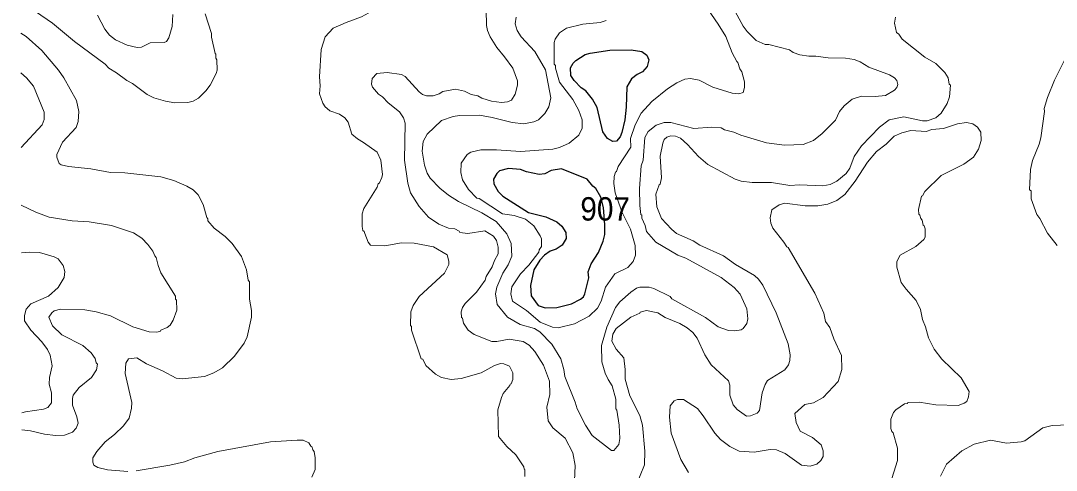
# Model space of a CAD drawing. Extents: x 447.8 to 473.9, y 7733.1 to 7760.8.
# Drawn here: x 447.849 to 451.388, y 7735.931 to 7737.469 of the extents above; entities that cross this region are included whole.
import ezdxf

# ---------------------------------------------------------------- set-up
doc = ezdxf.new("R2010")
doc.units = 0
doc.header["$LTSCALE"] = 0.032
doc.layers.add('1', color=7, linetype='Continuous', lineweight=25)
doc.layers.add('2', color=7, linetype='Continuous', lineweight=13)
doc.layers.add('21', color=7, linetype='Continuous')

msp = doc.modelspace()

# ---------------------------------------------------------------- linework, layer by layer
at = {"layer": '1'}
for points in [[(449.8538, 7737.0657), (449.8377, 7737.0891), (449.8186, 7737.1718), (449.8023, 7737.2009), (449.7799, 7737.2289), (449.7641, 7737.2393), (449.7396, 7737.2646), (449.7288, 7737.2812), (449.7277, 7737.3073), (449.7371, 7737.3243), (449.7459, 7737.3331), (449.7778, 7737.3529), (449.7946, 7737.3585), (449.8619, 7737.3681), (449.9348, 7737.3697), (449.9717, 7737.3633), (449.9879, 7737.351), (449.9949, 7737.3353), (449.9899, 7737.3128), (449.9731, 7737.2942), (449.9557, 7737.2856), (449.9363, 7737.2701), (449.9198, 7737.2433), (449.918, 7737.1727), (449.9131, 7737.1294), (449.9034, 7737.0865), (449.8967, 7737.0718), (449.8848, 7737.0564), (449.8724, 7737.0559)], [(449.7896, 7736.5891), (449.7883, 7736.6097), (449.7976, 7736.6376), (449.8226, 7736.6765), (449.8393, 7736.7146), (449.8446, 7736.7381), (449.8451, 7736.7711), (449.8403, 7736.83), (449.8314, 7736.8655), (449.8146, 7736.8952), (449.8042, 7736.9031), (449.7841, 7736.9264), (449.6967, 7736.9625), (449.6616, 7736.9561), (449.6403, 7736.9457), (449.6202, 7736.9426), (449.5773, 7736.9524), (449.5565, 7736.9602), (449.5156, 7736.9633), (449.4849, 7736.9551), (449.4756, 7736.9465), (449.4648, 7736.9273), (449.4651, 7736.9112), (449.4806, 7736.8846), (449.4965, 7736.8685), (449.5839, 7736.8125), (449.6426, 7736.7981), (449.6804, 7736.7808), (449.6984, 7736.7661), (449.7112, 7736.745), (449.7126, 7736.7242), (449.6995, 7736.7009), (449.6788, 7736.6875), (449.6584, 7736.6804), (449.6385, 7736.6669), (449.6225, 7736.6502), (449.6023, 7736.6162), (449.591, 7736.563), (449.5936, 7736.5282), (449.6175, 7736.4945), (449.6407, 7736.4865), (449.6811, 7736.4873), (449.7311, 7736.5006), (449.7622, 7736.5159), (449.7718, 7736.5239), (449.777, 7736.5349)]]:
    msp.add_lwpolyline(points, close=True, dxfattribs=at)
at = {"layer": '2'}
for points in [[(451.5688, 7737.5655), (451.4588, 7737.425), (451.4404, 7737.3933), (451.4375, 7737.3812), (451.4218, 7737.3529), (451.42, 7737.3431), (451.382, 7737.2653), (451.3575, 7737.2064)], [(447.8597, 7737.5276), (447.9567, 7737.4612), (448.0319, 7737.398), (448.1367, 7737.3202), (448.1492, 7737.3063), (448.1759, 7737.2908), (448.2112, 7737.2641), (448.2305, 7737.2547), (448.2802, 7737.2168), (448.3039, 7737.2053), (448.3434, 7737.1935), (448.3754, 7737.1879), (448.4197, 7737.1895), (448.4377, 7737.194), (448.456, 7737.204), (448.4815, 7737.2287), (448.4961, 7737.2489), (448.5167, 7737.2885), (448.5199, 7737.3), (448.5184, 7737.335), (448.5153, 7737.3404), (448.5152, 7737.3542), (448.5126, 7737.3572), (448.501, 7737.4132), (448.5008, 7737.4251), (448.4791, 7737.4928)], [(449.114, 7737.5314), (449.114, 7737.5248), (449.1095, 7737.517), (449.051, 7737.5029), (449.0128, 7737.4823), (448.9606, 7737.4634)], [(449.4387, 7737.5065), (449.4406, 7737.4525), (449.4438, 7737.4352), (449.453, 7737.4141), (449.4752, 7737.3773), (449.5017, 7737.346), (449.53, 7737.3064), (449.546, 7737.2636), (449.546, 7737.2484), (449.5389, 7737.2176), (449.5255, 7737.1972), (449.5121, 7737.191), (449.4911, 7737.1895), (449.4575, 7737.194), (449.4244, 7737.2046), (449.4111, 7737.2119), (449.3883, 7737.2169), (449.3654, 7737.2275), (449.3344, 7737.2351), (449.2907, 7737.2271), (449.2789, 7737.2193), (449.2577, 7737.2119), (449.2355, 7737.2117), (449.2217, 7737.2166), (449.2099, 7737.2252), (449.1624, 7737.2779), (449.1494, 7737.285), (449.1013, 7737.292), (449.0658, 7737.2881), (449.0495, 7737.2716), (449.0476, 7737.2523), (449.0509, 7737.2417), (449.0709, 7737.2175), (449.0848, 7737.2088), (449.1038, 7737.1886), (449.1434, 7737.1575), (449.1569, 7737.1371), (449.1629, 7737.1188), (449.1598, 7736.9923), (449.1711, 7736.913), (449.1807, 7736.8798), (449.2108, 7736.833), (449.2424, 7736.7974), (449.2778, 7736.7725), (449.3108, 7736.7597), (449.3327, 7736.7565)], [(450.1759, 7737.538), (450.2319, 7737.4576), (450.2579, 7737.4154), (450.2803, 7737.3593), (450.2957, 7737.3298), (450.2999, 7737.3264), (450.3058, 7737.3039), (450.3125, 7737.2938), (450.3217, 7737.2597), (450.3224, 7737.24), (450.3173, 7737.223), (450.3027, 7737.2191), (450.28, 7737.2215), (450.2137, 7737.2421), (450.167, 7737.2651), (450.138, 7737.2711), (450.1178, 7737.2686), (450.0914, 7737.2569), (450.0586, 7737.2361), (450.0052, 7737.1924), (449.9688, 7737.1524), (449.9487, 7737.113), (449.9325, 7737.0656), (449.9337, 7737.0365), (449.8909, 7736.97), (449.8842, 7736.9531), (449.8808, 7736.9513), (449.8764, 7736.9361), (449.8756, 7736.9125), (449.8796, 7736.8797), (449.9038, 7736.8123), (449.9328, 7736.7554), (449.9484, 7736.7004), (449.95, 7736.6669), (449.9411, 7736.6449), (449.9231, 7736.6246), (449.8792, 7736.6028), (449.8472, 7736.5571), (449.8318, 7736.5091), (449.8196, 7736.4859), (449.7916, 7736.4578), (449.7407, 7736.4314), (449.6858, 7736.4184), (449.666, 7736.42), (449.6237, 7736.438), (449.5771, 7736.477), (449.529, 7736.51)], [(450.2706, 7737.536), (450.318, 7737.4508), (450.3313, 7737.4316), (450.3624, 7737.4015), (450.393, 7737.3878), (450.4057, 7737.3881), (450.4764, 7737.3689), (450.4882, 7737.3604), (450.5108, 7737.3527), (450.5425, 7737.3474), (450.5661, 7737.3473), (450.6084, 7737.3418), (450.6674, 7737.3409), (450.6966, 7737.3366), (450.718, 7737.3281), (450.7472, 7737.3103)], [(448.111, 7737.4883), (448.1355, 7737.4401), (448.1524, 7737.4192), (448.1719, 7737.4036), (448.2128, 7737.3854), (448.2468, 7737.3771), (448.2617, 7737.3787), (448.2909, 7737.393), (448.3386, 7737.395), (448.3462, 7737.3981), (448.355, 7737.4109), (448.3661, 7737.4492), (448.3682, 7737.4908)], [(449.229, 7736.9748), (449.2202, 7737.0228), (449.2237, 7737.0561), (449.2375, 7737.0804), (449.287, 7737.1271), (449.3268, 7737.1414), (449.3486, 7737.1445), (449.4166, 7737.1461), (449.46, 7737.1384), (449.5284, 7737.1204), (449.5683, 7737.116), (449.6024, 7737.1229), (449.6184, 7737.1301), (449.6397, 7737.1517), (449.6539, 7737.1745), (449.6599, 7737.2051), (449.6423, 7737.301), (449.606, 7737.3636), (449.5584, 7737.4136), (449.545, 7737.4353), (449.5381, 7737.4585), (449.5419, 7737.4809)], [(449.6197, 7736.6766), (449.6208, 7736.6852), (449.6278, 7736.6967), (449.6278, 7736.7226), (449.6241, 7736.7335), (449.6016, 7736.7667), (449.5733, 7736.7902), (449.5351, 7736.8022), (449.4953, 7736.8083), (449.4156, 7736.8613), (449.407, 7736.8624), (449.379, 7736.8914), (449.3586, 7736.925), (449.3522, 7736.9493), (449.3538, 7736.9811), (449.3747, 7737.0114), (449.3874, 7737.0194), (449.421, 7737.0275), (449.4745, 7737.0276), (449.5569, 7737.0211), (449.6676, 7737.0291), (449.6897, 7737.0353), (449.7234, 7737.0504), (449.7555, 7737.0774), (449.7673, 7737.1011), (449.7672, 7737.1304), (449.756, 7737.1624), (449.7356, 7737.2), (449.6901, 7737.259), (449.6761, 7737.3062), (449.6759, 7737.3157), (449.6712, 7737.3203), (449.6712, 7737.3942), (449.675, 7737.4055), (449.6895, 7737.4274), (449.7135, 7737.4438), (449.7693, 7737.4572), (449.8288, 7737.4625), (449.8495, 7737.4703)], [(450.0301, 7736.9073), (450.0337, 7736.9096), (450.0382, 7736.9313), (450.0335, 7737.0053), (450.0431, 7737.0506), (450.0481, 7737.0623), (450.0571, 7737.0708), (450.0698, 7737.0756), (450.0863, 7737.074), (450.103, 7737.0672), (450.1278, 7737.0454), (450.1649, 7737.0043), (450.1967, 7736.9774), (450.29, 7736.9273), (450.3106, 7736.9201), (450.3486, 7736.9153), (450.414, 7736.916), (450.4769, 7736.9057), (450.5102, 7736.9072), (450.5903, 7736.9041), (450.6144, 7736.9091), (450.6375, 7736.9199), (450.6691, 7736.9465), (450.6825, 7736.9647), (450.6973, 7737.0045), (450.7223, 7737.0406), (450.7834, 7737.1049), (450.8167, 7737.13), (450.8664, 7737.1406), (450.9309, 7737.127), (450.9461, 7737.1266), (450.9755, 7737.1362), (450.9945, 7737.1525), (451.015, 7737.1856), (451.0226, 7737.2086), (451.0258, 7737.2484), (451.0211, 7737.2518), (451.0178, 7737.2733), (451.0071, 7737.2923), (450.9764, 7737.323), (450.9389, 7737.3449), (450.8605, 7737.406), (450.8494, 7737.4234), (450.8418, 7737.4291), (450.8351, 7737.4608), (450.8383, 7737.4817)], [(448.9606, 7737.4634), (448.9158, 7737.4433), (448.8891, 7737.4144), (448.875, 7737.371), (448.8696, 7737.2772), (448.8718, 7737.2462), (448.8696, 7737.2194), (448.8806, 7737.1865), (448.8886, 7737.1744), (448.8956, 7737.1685), (448.905, 7737.161), (448.9385, 7737.1493), (448.9559, 7737.1367), (448.9676, 7737.1215), (448.9803, 7737.0814), (448.9998, 7737.0647), (449.0205, 7737.0529), (449.0666, 7737.0195), (449.0789, 7736.9914), (449.085, 7736.9432), (449.0829, 7736.9323), (449.0743, 7736.9146), (449.07, 7736.911), (449.067, 7736.899), (449.0216, 7736.8265), (449.0155, 7736.8078), (449.0155, 7736.7655), (449.018, 7736.7514), (449.0219, 7736.748), (449.0244, 7736.7412), (449.0357, 7736.7111), (449.044, 7736.7006), (449.0931, 7736.6989), (449.1503, 7736.7094), (449.1931, 7736.7077), (449.259, 7736.6955), (449.3056, 7736.668), (449.312, 7736.6459), (449.312, 7736.6348), (449.2972, 7736.6048), (449.2103, 7736.5249), (449.1901, 7736.4952), (449.1823, 7736.4735), (449.1806, 7736.4258), (449.1837, 7736.4229), (449.184, 7736.4097), (449.2176, 7736.3119), (449.2224, 7736.3106), (449.2332, 7736.2894), (449.2659, 7736.26), (449.287, 7736.2481), (449.3193, 7736.2412), (449.354, 7736.2452), (449.4221, 7736.264), (449.4676, 7736.2893), (449.4877, 7736.2963), (449.4991, 7736.2953), (449.5191, 7736.287), (449.53, 7736.2644), (449.5308, 7736.2417), (449.5244, 7736.2263), (449.5213, 7736.2256), (449.5202, 7736.221), (449.4977, 7736.1939), (449.4913, 7736.1804), (449.4792, 7736.1379), (449.4819, 7736.047), (449.5094, 7736.0125), (449.5406, 7735.9836), (449.5685, 7735.9426), (449.5686, 7735.9352), (449.5717, 7735.933), (449.5717, 7735.91)], [(447.8485, 7737.4267), (447.867, 7737.4152), (447.9202, 7737.3676), (447.978, 7737.3003), (447.996, 7737.2741), (448.0387, 7737.1962), (448.0471, 7737.1589), (448.0449, 7737.1244), (448.0376, 7737.1032), (447.9915, 7737.0537), (447.9719, 7737.0116), (447.9718, 7737.0018), (447.9801, 7736.9809), (447.9867, 7736.9765), (448.0115, 7736.9698), (448.0885, 7736.9626), (448.1556, 7736.9502), (448.2046, 7736.9489), (448.3273, 7736.9346), (448.3719, 7736.9228), (448.4168, 7736.9035), (448.4383, 7736.8904), (448.4547, 7736.873), (448.4719, 7736.8399), (448.4846, 7736.7957), (448.488, 7736.7915), (448.4881, 7736.7841), (448.5099, 7736.7595), (448.5476, 7736.7307), (448.5711, 7736.7071), (448.6034, 7736.6619), (448.6203, 7736.6168), (448.6259, 7736.5814), (448.6306, 7736.5759), (448.6307, 7736.5158), (448.6371, 7736.478), (448.6371, 7736.4552), (448.6226, 7736.3878), (448.6124, 7736.3657), (448.5787, 7736.3208), (448.5378, 7736.2811), (448.5082, 7736.2641), (448.4764, 7736.2515), (448.4007, 7736.2436), (448.3801, 7736.2458), (448.3335, 7736.2711), (448.2781, 7736.2948), (448.2456, 7736.3157), (448.2169, 7736.3121), (448.2082, 7736.2973), (448.2058, 7736.2625), (448.2282, 7736.1623), (448.2274, 7736.1438), (448.2194, 7736.1092), (448.2003, 7736.0833), (448.1694, 7736.0533), (448.1375, 7736.0282), (448.109, 7735.9947), (448.0953, 7735.9739), (448.0953, 7735.9582), (448.0985, 7735.9487), (448.1119, 7735.9403), (448.1448, 7735.9326), (448.2143, 7735.927)], [(450.7472, 7737.3103), (450.8182, 7737.2836), (450.8344, 7737.2735), (450.8428, 7737.2648), (450.8462, 7737.2511), (450.843, 7737.24)], [(447.8489, 7737.2904), (447.8685, 7737.2734), (447.892, 7737.2449), (447.9286, 7737.1565), (447.9285, 7737.1314), (447.9216, 7737.1127), (447.8497, 7737.0358)], [(450.843, 7737.24), (450.8343, 7737.2319), (450.8035, 7737.2133), (450.7689, 7737.2103), (450.7225, 7737.211), (450.6898, 7737.2008), (450.6624, 7737.178), (450.6471, 7737.1583), (450.6328, 7737.1283), (450.5879, 7737.0826), (450.5579, 7737.0597), (450.5228, 7737.0457), (450.4593, 7737.0428), (450.3973, 7737.0512), (450.3095, 7737.0772), (450.2861, 7737.0879), (450.2537, 7737.0962), (450.2419, 7737.102), (450.2095, 7737.1052), (450.1489, 7737.0997), (450.07, 7737.1212), (450.0478, 7737.1212), (450.0199, 7737.1112), (449.9928, 7737.0903), (449.981, 7737.069), (449.9757, 7736.9922), (449.9694, 7736.973), (449.9638, 7736.8951), (449.9646, 7736.8372), (449.9678, 7736.8061), (449.9708, 7736.8035), (449.971, 7736.7938), (449.9821, 7736.7683), (449.9874, 7736.748), (450.0191, 7736.7117), (450.0939, 7736.6674), (450.1211, 7736.6561), (450.242, 7736.5902), (450.287, 7736.5566), (450.3068, 7736.5329), (450.33, 7736.4829), (450.3332, 7736.4487), (450.3298, 7736.4327), (450.3179, 7736.4165), (450.3107, 7736.4118), (450.2888, 7736.4079), (450.2672, 7736.4095), (450.2316, 7736.4212), (450.1883, 7736.4531), (450.0741, 7736.5179), (450.0684, 7736.525), (450.0126, 7736.5533), (449.9965, 7736.5577), (449.9641, 7736.5577), (449.9531, 7736.5536), (449.9338, 7736.5407), (449.8961, 7736.5077), (449.8813, 7736.4875), (449.8516, 7736.4202), (449.833, 7736.3582), (449.8348, 7736.3022), (449.8463, 7736.2633), (449.8561, 7736.2409), (449.8699, 7736.2195), (449.8827, 7736.1746), (449.8828, 7736.1413), (449.8862, 7736.137), (449.8939, 7736.0848), (449.8955, 7736.0399), (449.8923, 7736.019), (449.8757, 7735.9989), (449.8671, 7735.9983), (449.8014, 7736.05), (449.7784, 7736.0851), (449.7497, 7736.1409), (449.7431, 7736.1637), (449.7084, 7736.252), (449.7048, 7736.2756), (449.6942, 7736.312), (449.6637, 7736.3625), (449.6228, 7736.404), (449.6048, 7736.4161), (449.5554, 7736.4297), (449.512, 7736.4549), (449.4773, 7736.498), (449.4716, 7736.5342), (449.4753, 7736.5571), (449.4962, 7736.6055), (449.5145, 7736.6341), (449.5268, 7736.6637), (449.5251, 7736.7071), (449.5096, 7736.7399), (449.4732, 7736.7819), (449.4245, 7736.8117), (449.3451, 7736.8507)], [(451.3575, 7737.2064), (451.3465, 7737.1682), (451.3479, 7737.1586), (451.3353, 7737.0679), (451.3292, 7737.0462), (451.3068, 7736.9908)], [(450.5298, 7736.8352), (450.5728, 7736.8352), (450.6068, 7736.8419), (450.6372, 7736.854), (450.6646, 7736.874), (450.7007, 7736.9196), (450.7426, 7736.9856), (450.7731, 7737.0217), (450.8064, 7737.047), (450.8332, 7737.0738), (450.8599, 7737.086), (450.8911, 7737.0932), (450.9428, 7737.0901), (450.9629, 7737.0963), (451.002, 7737.0997), (451.0501, 7737.1157), (451.0811, 7737.1213), (451.1027, 7737.1163), (451.1188, 7737.1044), (451.13, 7737.0876), (451.1315, 7737.0593), (451.1214, 7737.029), (451.1045, 7737.0026), (451.0718, 7736.978), (450.9937, 7736.9393), (450.938, 7736.8851), (450.93, 7736.8704), (450.9266, 7736.8687), (450.9169, 7736.8226), (450.9177, 7736.8066), (450.9216, 7736.8036), (450.9246, 7736.7926), (450.9295, 7736.7862), (450.9329, 7736.769), (450.9359, 7736.7677), (450.9392, 7736.7565), (450.9392, 7736.7289), (450.9345, 7736.72), (450.9074, 7736.6966), (450.8543, 7736.6668), (450.8431, 7736.6456), (450.8433, 7736.6254), (450.8575, 7736.5734), (450.8741, 7736.55), (450.9088, 7736.5117), (450.9231, 7736.4808), (450.9304, 7736.4466), (450.9412, 7736.4221), (450.9508, 7736.3836), (450.9704, 7736.3448), (450.9961, 7736.3116), (451.0623, 7736.2476), (451.09, 7736.2008), (451.0877, 7736.1817), (451.0819, 7736.1667), (451.0728, 7736.1601), (451.0527, 7736.1521), (450.9757, 7736.1544), (450.9188, 7736.1634), (450.8802, 7736.1625), (450.8796, 7736.1595), (450.8691, 7736.1585), (450.8395, 7736.1382), (450.8312, 7736.129), (450.8223, 7736.1061), (450.8223, 7736.074), (450.8257, 7736.0633), (450.8301, 7736.0592), (450.8454, 7736.0063), (450.8445, 7735.9639), (450.8205, 7735.8849)], [(449.3451, 7736.8507), (449.311, 7736.8722), (449.2812, 7736.8962), (449.2476, 7736.9298), (449.2377, 7736.9479), (449.229, 7736.9748)], [(451.3068, 7736.9908), (451.3, 7736.9604), (451.2967, 7736.8907), (451.3015, 7736.8866), (451.3023, 7736.8595), (451.3216, 7736.8065), (451.3319, 7736.7921), (451.3575, 7736.7416), (451.3909, 7736.7002)], [(450.0896, 7736.7406), (450.0723, 7736.7554), (450.0389, 7736.7921), (450.0222, 7736.8322), (450.0191, 7736.8752), (450.0301, 7736.9073)], [(447.8503, 7736.8381), (447.8999, 7736.8141), (447.946, 7736.797), (448.0241, 7736.7839), (448.0821, 7736.7807), (448.159, 7736.7687), (448.2334, 7736.7428), (448.2619, 7736.7253), (448.2834, 7736.7039), (448.3002, 7736.6801), (448.3065, 7736.665), (448.312, 7736.6593), (448.3181, 7736.6312), (448.3271, 7736.607), (448.3773, 7736.5262), (448.3774, 7736.5165), (448.3806, 7736.5134), (448.3823, 7736.4784), (448.3696, 7736.4445), (448.3589, 7736.4279), (448.3488, 7736.4195), (448.3278, 7736.4101), (448.3267, 7736.4072), (448.3142, 7736.4039), (448.2873, 7736.4047), (448.2318, 7736.4215), (448.1552, 7736.4589), (448.1061, 7736.4729), (448.0676, 7736.4801), (447.9847, 7736.4818), (447.9634, 7736.4765), (447.9545, 7736.4691), (447.9447, 7736.455), (447.9568, 7736.4248), (447.9885, 7736.3948), (448.0605, 7736.3578), (448.0891, 7736.3331), (448.1032, 7736.3134), (448.1067, 7736.2987), (448.1112, 7736.2937), (448.108, 7736.2741), (448.0901, 7736.248), (448.0482, 7736.2142), (448.028, 7736.1879), (448.025, 7736.1767), (448.0255, 7736.1534), (448.0404, 7736.1132), (448.0448, 7736.0919), (448.0383, 7736.0747), (448.0255, 7736.0617), (447.9977, 7736.0512), (447.9674, 7736.0496), (447.9298, 7736.0544), (447.882, 7736.0664), (447.8527, 7736.0693)], [(450.4119, 7736.7762), (450.4103, 7736.7943), (450.4152, 7736.8222), (450.4404, 7736.8394), (450.4597, 7736.8447), (450.5298, 7736.8352)], [(450.1311, 7735.9232), (450.1044, 7735.9672), (450.0718, 7736.0583), (450.0656, 7736.1126), (450.0683, 7736.1513), (450.0813, 7736.168), (450.0931, 7736.1733), (450.1133, 7736.173), (450.1613, 7736.142), (450.1813, 7736.1175), (450.2209, 7736.0579), (450.2405, 7736.0365), (450.2721, 7736.0121), (450.3034, 7735.9961), (450.3551, 7735.9927), (450.4093, 7736.0015), (450.4311, 7736.0006), (450.4609, 7735.988), (450.5166, 7735.9483), (450.5467, 7735.9446), (450.5693, 7735.952), (450.5829, 7735.964), (450.5913, 7735.9783), (450.5906, 7735.9979), (450.5839, 7736.0177), (450.5541, 7736.0433), (450.5123, 7736.0647), (450.4982, 7736.0947), (450.4944, 7736.1246), (450.5284, 7736.1554), (450.5581, 7736.1612), (450.5911, 7736.1799), (450.6426, 7736.2351), (450.6546, 7736.2756), (450.6531, 7736.3234), (450.627, 7736.3804), (450.6139, 7736.4196), (450.5993, 7736.4394), (450.5928, 7736.4683), (450.5625, 7736.5369), (450.4714, 7736.6935), (450.4665, 7736.6957), (450.4566, 7736.7117), (450.4184, 7736.7589), (450.4119, 7736.7762)], [(449.3327, 7736.7565), (449.3473, 7736.7492), (449.3498, 7736.7439), (449.3765, 7736.7406), (449.4346, 7736.75), (449.4638, 7736.7321)], [(449.4638, 7736.7321), (449.4747, 7736.7165), (449.4804, 7736.6937), (449.4803, 7736.6719), (449.4673, 7736.6485), (449.4603, 7736.6268), (449.439, 7736.5936), (449.436, 7736.5816), (449.4061, 7736.5399), (449.3676, 7736.5019), (449.3583, 7736.4883), (449.3538, 7736.4731), (449.3546, 7736.4531), (449.3585, 7736.4508), (449.3621, 7736.4338), (449.378, 7736.4108), (449.3977, 7736.3955), (449.4586, 7736.3719), (449.4759, 7736.3711), (449.5182, 7736.3799), (449.5652, 7736.371), (449.5866, 7736.3593), (449.6058, 7736.3371), (449.6351, 7736.29), (449.6552, 7736.2352), (449.6567, 7736.1906), (449.6463, 7736.1469), (449.6513, 7736.1005), (449.6666, 7736.0766), (449.7095, 7736.0407), (449.7356, 7735.9907), (449.7432, 7735.9473), (449.7401, 7735.8685)], [(449.9505, 7735.8764), (449.9805, 7735.9496), (449.9813, 7735.9957), (449.9741, 7736.0848), (449.9644, 7736.1188), (449.9299, 7736.1861), (449.9147, 7736.2431), (449.9148, 7736.2756), (449.9092, 7736.3153), (449.8836, 7736.3455), (449.8684, 7736.3722), (449.8725, 7736.3961), (449.8834, 7736.4157), (449.9334, 7736.4546), (449.964, 7736.4686), (449.9653, 7736.4715), (449.987, 7736.4775), (450.0257, 7736.4695), (450.0513, 7736.4534), (450.101, 7736.4326), (450.1264, 7736.4183), (450.145, 7736.4028), (450.1601, 7736.383), (450.187, 7736.3259), (450.2079, 7736.2919), (450.2675, 7736.2372), (450.2723, 7736.2217), (450.2724, 7736.1875), (450.2839, 7736.1548), (450.297, 7736.1393), (450.3293, 7736.1155), (450.3431, 7736.117), (450.3658, 7736.1264), (450.3733, 7736.1357), (450.382, 7736.1959), (450.3925, 7736.2243), (450.401, 7736.2375), (450.46, 7736.2749), (450.4729, 7736.2911), (450.4775, 7736.307), (450.4782, 7736.326), (450.4713, 7736.3632), (450.4309, 7736.4699), (450.3853, 7736.5643), (450.3705, 7736.5847), (450.356, 7736.5969), (450.2918, 7736.6346), (450.2498, 7736.6651), (450.1695, 7736.7006), (450.1462, 7736.7161), (450.0896, 7736.7406)], [(447.8508, 7736.675), (447.878, 7736.6773), (447.9124, 7736.6758), (447.9627, 7736.6616), (447.9761, 7736.6542), (447.994, 7736.6318), (447.999, 7736.6106), (447.9971, 7736.5908), (447.9763, 7736.5567), (447.943, 7736.527), (447.8826, 7736.5005), (447.8675, 7736.4821), (447.8618, 7736.4605), (447.8619, 7736.4427), (447.8836, 7736.4104), (447.9206, 7736.37), (447.9397, 7736.3445), (447.9495, 7736.3247), (447.9565, 7736.2881), (447.9466, 7736.2483), (447.9462, 7736.226), (447.9542, 7736.1964), (447.9541, 7736.1614), (447.9416, 7736.1461), (447.9264, 7736.1397), (447.8651, 7736.1313), (447.8525, 7736.1276)], [(449.529, 7736.51), (449.5237, 7736.5342), (449.5272, 7736.5583), (449.5571, 7736.6032), (449.5856, 7736.6321), (449.6197, 7736.6766)], [(451.4305, 7736.0864), (451.3741, 7736.0841), (451.3419, 7736.0764), (451.2803, 7736.0314), (451.2682, 7736.028), (451.2171, 7736.0232), (451.1631, 7736.0344), (451.107, 7736.02), (451.0654, 7735.9974), (451.0128, 7735.9515), (450.9917, 7735.9108)], [(448.2432, 7735.9284), (448.3587, 7735.9483), (448.4085, 7735.96), (448.444, 7735.9735), (448.5223, 7735.9952), (448.7019, 7736.028), (448.7937, 7736.0344), (448.8134, 7736.0335), (448.8333, 7736.0247), (448.8404, 7736.0132), (448.8438, 7736.0126), (448.8472, 7736.0007), (448.8519, 7735.9955), (448.8552, 7735.9732), (448.8551, 7735.9337), (448.8437, 7735.9075)]]:
    msp.add_lwpolyline(points, dxfattribs=at)

# ---------------------------------------------------------------- texts
at = {"layer": '21', "width": 0.95}
msp.add_text('907', height=0.08, dxfattribs=at).set_placement((449.7612, 7736.7853))

doc.saveas('drawing.dxf')
